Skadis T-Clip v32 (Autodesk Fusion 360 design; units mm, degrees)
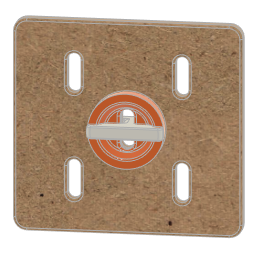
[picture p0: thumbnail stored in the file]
parameter "AttachmentSlotAngle" = 0
parameter "ClipLengthTolerance" = -0.1 comment "This determines how  tight  the clip fastens together."
parameter "PaintedSkadisThickness" = 5.25
parameter "UnpaintedSkadisThickness" = 4.82
parameter "ResultingClipLength" = 4.72 (= "SkadisBoardThickness + ClipLengthTolerance")
ground "Ground1"
sketch "Skadis Hole Dimensions" plane through (0, 0, 0) normal (0, 1, 0) x axis (1, 0, 0)
  line L1 (-2.5, -5) -> (-2.5, 5)
  line L2 (2.5, 5) -> (2.5, -5)
  line L3 (0, 7.5) -> (0, -7.5)
  arc A1 centre (0, -5) radius 2.5 clockwise from (2.5, -5) to (-2.5, -5)
  arc A2 centre (0, 5) radius 2.5 clockwise from (-2.5, 5) to (2.5, 5)
  point P8 (0, -7.5)
  point P9 (0, 7.5)
  point P10 (0, -7.5)
  point P11 (0, 7.5)
  point P1 (0, 0)
  point P3 (-2.5, -5)
  point P4 (2.5, -5)
  tangent L1 A1
  tangent A1 L2
  parallel L1 L2
  tangent L2 A2
  tangent L1 A2
  midpoint A1 P8
  midpoint A2 P9
  coincident P8 P10
  coincident P9 P11
  midpoint P1 L3
  vertical L3
  dimension "d1" distance P3 P4 = 5
  dimension "d39" distance P8 P9 = 15
sketch "Skadis Board Thickness" plane through (0, 0, 0) normal (1, 0, 0) x axis (0, 1, 0)
  line L1 (4.82, 0) -> (0, 0)
  point P1 (0, 0)
  point P2 (0, 0)
  point P3 (4.82, 0)
  horizontal L1
  coincident P1 P2
  dimension "SkadisBoardThickness" distance P2 P3 = 4.82 (= "UnpaintedSkadisThickness")
sketch "Reference Skadis Shape" plane through (0, 0, 0) normal (0, 1, 0) x axis (1, 0, 0)
  line L1 (2.5, 5) -> (2.5, -5)
  line L2 (-2.5, -5) -> (-2.5, 5)
  line L3 (22.5, -15) -> (22.5, -25)
  line L4 (17.5, -25) -> (17.5, -15)
  line L5 (20, -15) -> (20, -25)
  line L6 (0, 7.5) -> (0, -7.5)
  line L7 (2.5, 0) -> (-2.5, 0)
  line L8 (17.5, 25) -> (17.5, 15)
  line L9 (22.5, 15) -> (22.5, 25)
  line L10 (-17.5, -25) -> (-17.5, -15)
  line L11 (-22.5, -15) -> (-22.5, -25)
  line L12 (-17.5, 25) -> (-17.5, 15)
  line L13 (-22.5, 15) -> (-22.5, 25)
  line L14 (-37.5, 40) -> (37.5, 40)
  line L15 (-42.5, -35) -> (-42.5, 35)
  line L16 (37.5, -40) -> (-37.5, -40)
  line L17 (42.5, 35) -> (42.5, -35)
  line L18 (-42.5, -40) -> (42.5, 40)
  line L19 (42.5, -40) -> (-42.5, 40)
  line L20 (0, 40) -> (0, -40)
  arc A1 centre (0, -5) radius 2.5 clockwise from (2.5, -5) to (-2.5, -5)
  arc A2 centre (0, 5) radius 2.5 clockwise from (-2.5, 5) to (2.5, 5)
  arc A3 centre (20, -15) radius 2.5 clockwise from (17.5, -15) to (22.5, -15)
  arc A4 centre (20, -25) radius 2.5 clockwise from (22.5, -25) to (17.5, -25)
  arc A5 centre (20, 25) radius 2.5 clockwise from (17.5, 25) to (22.5, 25)
  arc A6 centre (20, 15) radius 2.5 clockwise from (22.5, 15) to (17.5, 15)
  arc A7 centre (-20, -25) radius 2.5 clockwise from (-17.5, -25) to (-22.5, -25)
  arc A8 centre (-20, -15) radius 2.5 clockwise from (-22.5, -15) to (-17.5, -15)
  arc A9 centre (-20, 15) radius 2.5 clockwise from (-17.5, 15) to (-22.5, 15)
  arc A10 centre (-20, 25) radius 2.5 clockwise from (-22.5, 25) to (-17.5, 25)
  arc A11 centre (-37.5, -35) radius 5 clockwise from (-37.5, -40) to (-42.5, -35)
  arc A12 centre (37.5, -35) radius 5 clockwise from (42.5, -35) to (37.5, -40)
  arc A13 centre (37.5, 35) radius 5 clockwise from (37.5, 40) to (42.5, 35)
  arc A14 centre (-37.5, 35) radius 5 clockwise from (-42.5, 35) to (-37.5, 40)
  point P18 (20, -20)
  point P19 (0, -7.5)
  point P20 (0, 7.5)
  point P21 (0, 0)
  point P22 (-2.5, 0)
  point P23 (2.5, 0)
  point P12 (22.5, -25)
  point P27 (22.5, 25)
  point P13 (22.5, -15)
  point P29 (22.5, 15)
  point P14 (17.5, -15)
  point P24 (17.5, 15)
  point P15 (17.5, -25)
  point P25 (17.5, 25)
  point P33 (-22.5, -25)
  point P35 (-22.5, -15)
  point P30 (-17.5, -15)
  point P31 (-17.5, -25)
  point P37 (-17.5, 15)
  point P39 (-17.5, 25)
  point P41 (-22.5, 25)
  point P38 (-22.5, 15)
  point P46 (0, 0)
  point P44 (-42.5, -40)
  point P45 (42.5, -40)
  point P42 (42.5, 40)
  point P43 (-42.5, 40)
  point P59 (0, -40)
  point P60 (0, 40)
  point P6 (0, -5)
  point P17 (20, -15)
  tangent L3 A3
  tangent A3 L4
  parallel L3 L4
  tangent L4 A4
  tangent L3 A4
  vertical L5
  midpoint L5 P18
  equal A1 A4
  equal L1 L3
  midpoint A1 P19
  midpoint A2 P20
  coincident L6 P21
  midpoint L6 P21
  midpoint L2 P22
  midpoint L1 P23
  symmetric P12 L7 P27
  symmetric P13 L7 P29
  symmetric P14 L7 P24
  symmetric P15 L7 P25
  symmetric A3 L7 A6
  symmetric A4 L7 A5
  symmetric P12 L6 P33
  symmetric P13 L6 P35
  symmetric P14 L6 P30
  symmetric P15 L6 P31
  symmetric A3 L6 A8
  symmetric A4 L6 A7
  symmetric L6 P24 P37
  symmetric L6 P25 P39
  symmetric L6 P27 P41
  symmetric L6 A5 A10
  symmetric L6 P29 P38
  symmetric L6 A6 A9
  horizontal L14
  perpendicular L14 L15
  parallel L14 L16
  parallel L15 L17
  coincident L18 P46
  coincident L19 P46
  coincident P21 P46
  coincident P44 L15
  coincident P44 L16
  tangent L15 A11
  tangent L16 A11
  coincident P45 L16
  coincident P45 L17
  tangent L16 A12
  tangent L17 A12
  coincident P42 L17
  coincident P42 L14
  tangent L17 A13
  tangent L14 A13
  equal A12 A13
  coincident P43 L14
  coincident P43 L15
  tangent L14 A14
  tangent L15 A14
  equal A12 A14
  equal A11 A12
  midpoint L16 P59
  midpoint L14 P60
  dimension "d4" distance P6 P17 = 20
  dimension "d5" distance P18 P21 = 20
  dimension "d6" distance P33 L15 = 20
  dimension "d7" distance P18 L16 = 20
  dimension "d8" radius A11 = 5
extrude "Extrude1" sketch "Reference Skadis Shape" profile of L1 A1 A2 L2 L3 A3 L4 A4 L8 A5 A6 L9 L10 A7 A8 L11 A9 L12 A10 L13 L14 L15 L16 L17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 to an object
fillet "Fillet1" radius 1
sketch "Cross Section Cut Profile" plane through (0, 0, 0) normal (0, 1, 0) x axis (1, 0, 0)
  line L1 (37.5, -40) -> (-37.5, -40)
  line L2 (-37.5, 40) -> (37.5, 40)
  line L3 (-42.5, -35) -> (-42.5, 35)
  line L4 (0, 40) -> (0, -40)
  line L5 (-42.5, -40) -> (-37.5, -40)
  line L6 (-42.5, -40) -> (-42.5, -35)
  line L7 (-42.5, 40) -> (-42.5, 35)
  line L8 (-37.5, 40) -> (-42.5, 40)
  point P8 (0, -40)
  point P9 (0, 40)
  point P2 (-37.5, -40)
  point P10 (-37.5, -40)
  point P7 (-42.5, -35)
  point P12 (-42.5, -35)
  point P6 (-42.5, 35)
  point P13 (-42.5, 35)
  point P5 (-37.5, 40)
  point P15 (-37.5, 40)
  midpoint L1 P8
  coincident L2 P9
  vertical L4
  coincident P2 P10
  coincident P7 P12
  collinear L3 L6
  collinear L1 L5
  coincident P6 P13
  coincident P5 P15
  collinear L2 L8
  collinear L3 L7
extrude "Extrude2" cut sketch "Cross Section Cut Profile" no distance stored
sketch "Part Minimum Thickness" plane through (0, 0, 0) normal (1, 0, 0) x axis (0, 1, 0)
  line L1 (0, -7.5) -> (0, 7.5)
  line L2 (-2.4, 0) -> (0, 0)
  point P6 (0, 0)
  point P7 (-2.4, 0)
  perpendicular L1 L2
  midpoint L1 P6
  dimension "PartMinimumThickness" distance P6 P7 = 2.4
sketch "End Peg Tolerance" plane through (0, 0, 0) normal (0, 1, 0) x axis (1, 0, 0)
  line L1 (-2.5, -5) -> (-2.5, 5)
  line L2 (2.5, 5) -> (2.5, -5)
  line L3 (2.4, 5) -> (2.4, -5)
  line L4 (-2.4, -5) -> (-2.4, 5)
  line L5 (0, 7.4) -> (0, -7.4)
  line L6 (2.4, 0) -> (-2.4, 0)
  arc A1 centre (0, 5) radius 2.5 clockwise from (-2.5, 5) to (2.5, 5)
  arc A2 centre (0, -5) radius 2.5 clockwise from (2.5, -5) to (-2.5, -5)
  arc A3 centre (0, -5) radius 2.4 clockwise from (2.4, -5) to (-2.4, -5)
  arc A4 centre (0, 5) radius 2.4 clockwise from (-2.4, 5) to (2.4, 5)
  point P18 (0, -7.4)
  point P19 (0, 7.4)
  point P20 (-2.4, 0)
  point P21 (2.4, 0)
  midpoint A3 P18
  midpoint A4 P19
  coincident L4 P20
  coincident L3 P21
  midpoint L4 P20
  midpoint L3 P21
  dimension "EndPegTolerance" = -0.1
sketch "End Peg Length" plane through (0, 0, 0) normal (1, 0, 0) x axis (0, 1, 0)
  line L1 (0, -7.4) -> (0, 7.4)
  line L2 (4.72, 7.4) -> (0, 7.4)
  line L3 (4.72, -7.4) -> (0, -7.4)
  line L4 (4.72, -7.4) -> (4.72, 7.4)
  line L5 (4.82, 0) -> (0, 0)
  line L6 (9.72, 7.4) -> (4.72, 7.4)
  line L7 (9.72, -7.4) -> (9.72, 7.4)
  line L8 (4.72, -7.4) -> (9.72, -7.4)
  point P2 (0, 7.4)
  point P4 (0, 7.4)
  point P3 (0, -7.4)
  point P6 (0, -7.4)
  point P5 (4.72, 7.4)
  point P10 (9.72, 7.4)
  coincident P2 P4
  perpendicular L1 L2
  coincident P3 P6
  perpendicular L1 L3
  parallel L1 L4
  perpendicular L4 L6
  perpendicular L4 L8
  parallel L4 L7
  dimension "d20" distance P5 P10 = 5
  dimension "d115" distance P4 P5 = 4.72 (= "ResultingClipLength")
extrude "Extrude2" sketch "End Peg Tolerance" profile of A3 L4 L3 A4 to an object
sketch "End Twist Position" plane through (0, 0, 0) normal (0, 1, 0) x axis (1, 0, 0)
  line L1 (-2.5, -5) -> (-2.5, 5)
  line L2 (2.5, 5) -> (2.5, -5)
  line L3 (0, 7.5) -> (0, -7.5)
  line L4 (5, -2.5) -> (-5, -2.5)
  line L5 (-5, 2.5) -> (5, 2.5)
  line L6 (7.5, 0) -> (-7.5, 0)
  arc A1 centre (0, 5) radius 2.5 clockwise from (-2.5, 5) to (2.5, 5)
  arc A2 centre (0, -5) radius 2.5 clockwise from (2.5, -5) to (-2.5, -5)
  arc A3 centre (5, 0) radius 2.5 clockwise from (5, 2.5) to (5, -2.5)
  arc A4 centre (-5, 0) radius 2.5 clockwise from (-5, -2.5) to (-5, 2.5)
  point P20 (-7.5, 0)
  point P21 (7.5, 0)
  point P22 (0, 0)
  point P1 (0, 0)
  tangent L4 A3
  tangent A3 L5
  parallel L4 L5
  tangent L5 A4
  tangent L4 A4
  midpoint A4 P20
  midpoint A3 P21
  coincident L3 P22
  midpoint L3 P22
  midpoint P1 L6
  equal L3 L6
  equal A2 A3
  dimension "TwistLimitAngle" angle L3 L6 = 90
sketch "Twist Shaft Profile" plane through (0, 0, 0) normal (0, 1, 0) x axis (1, 0, 0)
  line L1 (-5, 2.5) -> (5, 2.5)
  line L2 (5, -2.5) -> (-5, -2.5)
  line L3 (-2.4, -5) -> (-2.4, 5)
  line L4 (2.4, 5) -> (2.4, -5)
  line L5 (0, 2.5) -> (0, -2.5)
  line L6 (-2.4, 0) -> (2.4, 0)
  line L7 (0, -2.5) -> (0.672, -2.304)
  line L8 (0, 2.5) -> (-0.672, 2.304)
  line L9 (0, 2.5) -> (0, -2.5)
  line L10 (-2.4, -2.5) -> (0, -2.5)
  line L11 (2.4, 2.5) -> (0, 2.5)
  line L12 (1.7313, 1.8035) -> (2.4, 2.5)
  line L13 (-1.7313, -1.8035) -> (-2.4, -2.5)
  arc A1 centre (-5, 0) radius 2.5 clockwise from (-5, -2.5) to (-5, 2.5)
  arc A2 centre (5, 0) radius 2.5 clockwise from (5, 2.5) to (5, -2.5)
  arc A3 centre (0, 5) radius 2.4 clockwise from (-2.4, 5) to (2.4, 5)
  arc A4 centre (0, -5) radius 2.4 clockwise from (2.4, -5) to (-2.4, -5)
  arc A5 centre (0, 0) radius 2.4 clockwise from (2.4, 0) to (0.672, -2.304)
  arc A6 centre (0, 0) radius 2.4 clockwise from (-2.4, 0) to (-0.672, 2.304)
  arc A7 centre (0, 0) radius 2.5 clockwise from (0, -2.5) to (-1.7313, -1.8035)
  arc A8 centre (0, 0) radius 2.5 clockwise from (0, 2.5) to (1.7313, 1.8035)
  point P22 (0, -2.5)
  point P23 (0, 2.5)
  point P24 (2.4, 0)
  point P25 (-2.4, 0)
  point P1 (0, 0)
  point P26 (0, 0)
  point P28 (0, 0)
  point P32 (0, 0)
  point P33 (-2.4, -2.5)
  point P34 (2.4, 2.5)
  point P35 (0, 0)
  point P31 (0, -2.5)
  point P37 (0, 0)
  coincident L2 P22
  coincident L1 P23
  perpendicular L1 L5
  midpoint L2 P22
  midpoint L4 P24
  midpoint L3 P25
  coincident P1 P26
  tangent A5 L7
  coincident P26 P28
  tangent A6 L8
  midpoint L9 P32
  coincident L3 P33
  coincident L4 P34
  coincident P1 P35
  coincident P31 A7
  tangent L10 A7
  coincident P28 P37
  tangent L11 A8
  collinear L12 L13
  dimension "d85" angle L6 L9 = 90 (= "TwistLimitAngle")
extrude "Extrude1" sketch "Twist Shaft Profile" profile of L3 L4 A5 L7 A6 L8 L10 L11 A7 A8 to an object
chamfer "Chamfer1" distance 1.5
extrude "Extrude3" sketch "Twist Shaft Profile" profile of L3 L4 to an object
sketch "M3 Position" plane through (0, 0, 0) normal (1, 0, 0) x axis (0, 1, 0)
  line L1 (-2.4, 0) -> (0, 0)
  line L2 (-5.58, 2.65) -> (-5.58, 1.47)
  line L3 (-8.67, 2.65) -> (-5.58, 2.65)
  line L4 (-8.67, -2.65) -> (-8.67, 2.65)
  line L5 (-5.58, -2.65) -> (-8.67, -2.65)
  line L6 (-5.58, -1.47) -> (-5.58, -2.65)
  line L7 (8.42, -1.47) -> (-5.58, -1.47)
  line L8 (8.42, 1.47) -> (8.42, -1.47)
  line L9 (-5.58, 1.47) -> (8.42, 1.47)
  line L10 (9.92, -7.4) -> (9.92, 7.4)
  line L11 (8.42, 0) -> (9.92, 0)
  line L12 (-5.58, -1.47) -> (-5.58, 1.47)
  line L13 (-8.67, 0) -> (8.42, 0)
  point P14 (9.92, 0)
  point P15 (8.42, 0)
  point P16 (-8.67, 0)
  point P6 (-8.67, 2.65)
  point P7 (-8.67, -2.65)
  point P10 (8.42, -1.47)
  point P11 (8.42, 1.47)
  point P5 (-5.58, 2.65)
  point P4 (-5.58, 1.47)
  point P3 (-2.4, 0)
  perpendicular L2 L3
  perpendicular L3 L4
  perpendicular L4 L5
  perpendicular L5 L6
  perpendicular L6 L7
  horizontal L9
  collinear L2 L6
  equal L2 L6
  midpoint L10 P14
  midpoint L8 P15
  horizontal L11
  parallel L7 L9
  perpendicular L8 L9
  midpoint L4 P16
  dimension "d60" distance P6 P7 = 5.3
  dimension "d61" distance P10 P11 = 2.94
  dimension "d62" distance P5 P6 = 3.09
  dimension "d63" distance P14 P15 = 1.5
  dimension "d64" distance P4 P11 = 14
  dimension "d95" distance P3 P4 = 3.18
revolve "Revolve1" sketch "M3 Position" AlongAngle 360
sketch "Hex Hole (Decorative)" plane through (0, -8.67, 0) normal (0, -1, 0) x axis (1, 0, 0)
  line L1 (-1.2341, 0.7125) -> (0, 1.425)
  line L2 (-1.2341, -0.7125) -> (-1.2341, 0.7125)
  line L3 (0, -1.425) -> (-1.2341, -0.7125)
  line L4 (1.2341, -0.7125) -> (0, -1.425)
  line L5 (1.2341, 0.7125) -> (1.2341, -0.7125)
  line L6 (0, 1.425) -> (1.2341, 0.7125)
  circle C1 centre (0, 0) radius 2.65
  point P2 (0, 0)
  point P9 (0, 0)
  point P4 (-1.2341, 0.7125)
  point P7 (1.2341, -0.7125)
  coincident P2 P9
  vertical L2
  dimension "d68" distance P4 P7 = 2.85
extrude "Extrude1" cut sketch "Hex Hole (Decorative)" profile of L1 L2 L3 L4 L5 L6 against normal blind 1.7
fillet "Fillet1" radius 0.1
sketch "Handle Space Limitations" plane through (0, 0, 0) normal (0, 1, 0) x axis (1, 0, 0)
  line L1 (20, -15) -> (20, -25)
  line L2 (22.5, -15) -> (22.5, -25)
  line L3 (17.5, -25) -> (17.5, -15)
  line L4 (0, 7.5) -> (0, -7.5)
  arc A1 centre (20, -15) radius 2.5 clockwise from (17.5, -15) to (22.5, -15)
  arc A2 centre (20, -25) radius 2.5 clockwise from (22.5, -25) to (17.5, -25)
  circle C1 centre (20, -20) radius 14.1421
  circle C2 centre (0, 0) radius 14.1421
  point P14 (20, -20)
  point P17 (0, 0)
  midpoint L1 P14
  coincident L4 P17
  tangent C1 C2
  midpoint L4 P17
  equal C1 C2
  dimension "d142" diameter C2 = 28.2843
as_built_joint "As-built1" OffsetX 0 OffsetY 0 OffsetZ 0 AngleZ 0
sketch "Attachment Slot Angle" plane through (0, 0, 0) normal (0, 1, 0) x axis (1, 0, 0)
  line L1 (-2.4, -5) -> (-2.4, 5)
  line L2 (2.4, 5) -> (2.4, -5)
  line L3 (0, -5) -> (0, 5)
  line L4 (2.6, 0) -> (0, 0)
  line L5 (-2.6, -5) -> (-2.6, 5)
  line L6 (2.6, 5) -> (2.6, -5)
  line L7 (-2.4, -5) -> (-2.4, 5)
  line L8 (2.4, 5) -> (2.4, -5)
  line L9 (0, 7.4) -> (0, -7.4)
  arc A1 centre (0, -5) radius 2.4 clockwise from (2.4, -5) to (-2.4, -5)
  arc A2 centre (0, 5) radius 2.4 clockwise from (-2.4, 5) to (2.4, 5)
  arc A3 centre (0, 5) radius 2.6 clockwise from (-2.6, 5) to (2.6, 5)
  arc A4 centre (0, -5) radius 2.6 clockwise from (2.6, -5) to (-2.6, -5)
  arc A5 centre (0, 5) radius 2.4 clockwise from (-2.4, 5) to (2.4, 5)
  arc A6 centre (0, -5) radius 2.4 clockwise from (2.4, -5) to (-2.4, -5)
  point P1 (0, 0)
  point P8 (0, 0)
  point P9 (0, 0)
  point P10 (2.6, 0)
  tangent L1 A1
  tangent A1 L2
  parallel L1 L2
  tangent L2 A2
  tangent L1 A2
  coincident P1 P8
  midpoint L3 P8
  coincident P1 P9
  horizontal L4
  equal L2 L8
  equal A1 A6
  coincident P10 L6
  dimension "d90" angle L3 L4 = 90 (= "AttachmentSlotAngle + 90 deg")
  dimension "AttachmentSlotTolerance" = 0.2
position "Position1"
sketch "Minimum Material Profile" plane through (0, 0, 0) normal (0, 1, 0) x axis (1, 0, 0)
  line L1 (2.6, 5) -> (2.6, -5)
  line L2 (-2.6, -5) -> (-2.6, 5)
  line L3 (2.5, -2.4) -> (2.5, 0)
  line L4 (-2.5, 2.4) -> (-2.5, 0)
  line L5 (0, 3.4655) -> (0, -3.4655)
  circle C1 centre (0, 0) radius 14.1421
  arc A1 centre (0, 5) radius 2.6 clockwise from (-2.6, 5) to (2.6, 5)
  arc A2 centre (0, -5) radius 2.6 clockwise from (2.6, -5) to (-2.6, -5)
  arc A3 centre (0, 0) radius 3.4655 clockwise from (-2.5, 2.4) to (0, 3.4655)
  arc A4 centre (0, 0) radius 3.4655 clockwise from (2.5, -2.4) to (0, -3.4655)
  point P15 (-2.5, 2.4)
  point P19 (-2.5, 2.4)
  point P2 (0, 0)
  point P17 (0, 0)
  point P14 (2.5, -2.4)
  point P22 (2.5, -2.4)
  point P20 (0, 0)
  point P1 (0, 0)
  coincident P15 P19
  coincident P2 P17
  coincident P14 P22
  coincident P17 P20
  midpoint P1 L5
  vertical L5
extrude "Extrude1" new body sketch "Minimum Material Profile" profile of C1 A1 L1 A2 L2 L3 L4 A3 A4 to an object bodies "Attached Part"
sketch "(Reference) Diameter of Slot" plane through (0, 0, 0) normal (0, 1, 0) x axis (1, 0, 0)
  arc A1 centre (0, 5) radius 2.6 clockwise from (-2.6, 5) to (2.6, 5)
  arc A2 centre (0, -5) radius 2.6 clockwise from (2.6, -5) to (-2.6, -5)
  circle C1 centre (0, 0) radius 7.6
  point P1 (0, 0)
  point P8 (0, 0)
  point P9 (0, -7.6)
  coincident P1 P8
  midpoint A2 P9
  coincident C1 P9
sketch "Handle Seat Profile" plane through (0, 0, 0) normal (1, 0, 0) x axis (0, 1, 0)
  line L1 (0, 7.6) -> (0, -7.6)
  line L2 (-2.4, 0) -> (0, 0)
  line L3 (-2.4, -7.7) -> (-2.4, 7.7)
  line L4 (-2.4, 7.6) -> (0, 7.6)
  line L5 (-5.4, 10.6836) -> (-2.7572, 8.466)
  line L6 (-5.4, 14.1421) -> (0, 14.1421)
  line L7 (-5.4, 10.6836) -> (-5.4, 14.1421)
  line L8 (-2.4, 14.1421) -> (-2.4, 7.7)
  arc A1 centre (-3.4, 7.7) radius 1 clockwise from (-2.7572, 8.466) to (-2.4, 7.7)
  point P5 (-2.4, 0)
  point P3 (0, 7.6)
  point P8 (0, 7.6)
  point P12 (0, 14.1421)
  point P14 (0, 14.1421)
  point P16 (-2.4, 14.1421)
  point P17 (-2.4, 7.6)
  point P6 (-2.4, 7.7)
  point P11 (-5.4, 10.6836)
  parallel L1 L3
  midpoint P5 L3
  coincident P3 P8
  horizontal L4
  tangent L3 A1
  tangent A1 L5
  coincident P12 P14
  horizontal L6
  vertical L7
  coincident L6 P16
  tangent A1 L8
  parallel L3 L8
  coincident L3 P17
  dimension "d97" angle L4 L5 = 40
  dimension "d98" radius A1 = 1
  dimension "d99" distance P6 P11 = 3
  dimension "d138" distance P6 P17 = 0.1
revolve "Revolve1" sketch "Handle Seat Profile" AlongAngle 360
as_built_joint "As-built2" OffsetX 0 OffsetY 0 OffsetZ 0 AngleZ 0
sketch "Handle Tolerances" plane through (0, 0, 0) normal (1, 0, 0) x axis (0, 1, 0)
  line L1 (-2.7572, 8.466) -> (-5.4, 10.6836)
  line L2 (-2.755, 8.3989) -> (-5.401, 10.6192)
  line L3 (-2.4, 0) -> (0, 0)
  line L4 (-2.4, 0) -> (-2.4, 7.7)
  line L5 (-5.4, 14.1421) -> (0, 14.1421)
  line L6 (-5.401, 14.1421) -> (-5.4, 14.1421)
  line L7 (-5.401, 10.6192) -> (-5.401, 14.1421)
  arc A1 centre (-3.4, 7.7) radius 1 between (-2.4, 7.7) and (-2.7572, 8.466)
  arc A2 centre (-3.3977, 7.6328) radius 1 clockwise from (-2.755, 8.3989) to (-2.4, 7.7)
  point P1 (0, 0)
  point P11 (0, 0)
  point P3 (-2.4, 7.7)
  point P13 (-2.4, 7.7)
  point P9 (-2.4, 7.7)
  point P15 (-5.4, 14.1421)
  point P16 (-5.4, 14.1421)
  point P5 (-5.4, 10.6836)
  point P7 (-5.401, 10.6192)
  parallel L1 L2
  tangent L2 A2
  equal A1 A2
  coincident P1 P11
  horizontal L3
  coincident P3 P13
  vertical L4
  coincident P9 P13
  coincident P15 P16
  parallel L5 L6
  vertical L7
  dimension "d102" distance L1 L2 = 0.05
  dimension "d104" distance P5 P7 = 0.001
sketch "Handle Profile" plane through (0, 0, 0) normal (1, 0, 0) x axis (0, 1, 0)
  line L1 (-2.4, 0) -> (-2.4, 7.7)
  line L2 (-2.755, 8.3989) -> (-5.401, 10.6192)
  line L3 (-5.401, 10.6192) -> (-5.401, 14.1421)
  line L4 (-7.4, 14.1421) -> (-5.401, 14.1421)
  line L5 (-8.9, 0) -> (-8.9, 12.6421)
  line L6 (-2.4, 0) -> (-8.9, 0)
  arc A1 centre (-3.3977, 7.6328) radius 1 clockwise from (-2.755, 8.3989) to (-2.4, 7.7)
  arc A2 centre (-7.4, 12.6421) radius 1.5 clockwise from (-8.9, 12.6421) to (-7.4, 14.1421)
  point P9 (-5.401, 14.1421)
  point P11 (-5.401, 14.1421)
  point P3 (-2.4, 0)
  point P16 (-2.4, 0)
  point P15 (-8.9, 0)
  coincident P9 P11
  perpendicular L3 L4
  tangent L4 A2
  tangent A2 L5
  coincident P3 P16
  horizontal L6
  vertical L5
  dimension "d105" radius A2 = 1.5
  dimension "d106" distance P15 P16 = 6.5
revolve "Revolve1" sketch "Handle Profile" AlongAngle 360
sketch "Cut Handle Flat" plane through (0, 0, 0) normal (0, 1, 0) x axis (1, 0, 0)
  line L1 (-2.4, -5) -> (-2.4, 5)
  line L2 (2.4, 5) -> (2.4, -5)
  line L3 (-2.4, 13.937) -> (-2.4, 5)
  line L4 (-2.4, -13.937) -> (-2.4, -5)
  line L5 (2.4, -13.937) -> (2.4, -5)
  line L6 (2.4, 13.937) -> (2.4, 5)
  circle C1 centre (0, 0) radius 14.1421
  point P2 (-2.4, 5)
  point P7 (-2.4, 5)
  point P8 (-2.4, 13.937)
  point P3 (-2.4, -5)
  point P9 (-2.4, -5)
  point P10 (-2.4, -13.937)
  point P4 (2.4, -5)
  point P11 (2.4, -5)
  point P12 (2.4, -13.937)
  point P5 (2.4, 5)
  point P13 (2.4, 5)
  point P14 (2.4, 13.937)
  coincident P2 P7
  coincident C1 P8
  coincident P3 P9
  coincident C1 P10
  coincident P4 P11
  coincident C1 P12
  coincident P5 P13
  coincident C1 P14
  collinear L2 L6
  collinear L2 L5
  collinear L1 L4
  collinear L1 L3
extrude "Extrude5" cut sketch "Cut Handle Flat" no distance stored
chamfer "Chamfer3" distance 0.5
chamfer "Chamfer4" distance 0.6 distance 1
fillet "Fillet4" radius 2
fillet "Fillet3" radius 1
sketch "Fastener Diameters" plane through (0, 0, 0) normal (0, 1, 0) x axis (1, 0, 0)
  circle C1 centre (0, 0) radius 1.47
  circle C2 centre (0, 0) radius 2.65
  circle C3 centre (0, 0) radius 1.6011
  circle C4 centre (0, 0) radius 2.75
  point P4 (0, 0)
  point P5 (0, 0)
  point P2 (0, -1.47)
  point P3 (0, -2.65)
  point P7 (0, 0)
  coincident P4 P5
  coincident P2 C1
  concentric C1 C2
  coincident P3 C2
  coincident P4 P7
  concentric C2 C4
  dimension "d116" distance C1 C3 = 0.1311
  dimension "d117" distance C2 C4 = 0.1
extrude "Extrude6" sketch "Fastener Diameters" profile of C3 blind -53.225
extrude "Extrude7" sketch "Fastener Diameters" profile of C3 C4 no distance stored
sketch "Aesthetic Stoppers" plane through (0, 0, 0) normal (0, 1, 0) x axis (1, 0, 0)
  line L1 (0, -5) -> (0, 5)
  line L2 (7.3861, 1.3024) -> (-7.3861, -1.3024)
  line L3 (9.6519, 4.342) -> (-10.5549, 0.779)
  line L4 (10.5549, -0.779) -> (-9.6519, -4.342)
  line L5 (-2.6, 10.2593) -> (-2.6, -10.2593)
  line L6 (2.6, 10.2593) -> (2.6, -10.2593)
  line L7 (-2.6, 0) -> (2.6, 0)
  line L8 (-0.4515, 2.5605) -> (0.4515, -2.5605)
  circle C1 centre (0, 0) radius 10.5836
  arc A1 centre (0, -5) radius 2.6 clockwise from (2.6, -5) to (-2.6, -5)
  point P7 (-10.5549, 0.779)
  point P8 (9.6519, 4.342)
  point P9 (-9.6519, -4.342)
  point P10 (10.5549, -0.779)
  point P11 (-2.6, -10.2593)
  point P12 (-2.6, 10.2593)
  point P13 (2.6, -10.2593)
  point P14 (2.6, 10.2593)
  point P15 (2.6, 0)
  point P1 (0, 0)
  point P16 (-2.6, 0)
  point P17 (0.4515, -2.5605)
  point P18 (-0.4515, 2.5605)
  point P19 (-2.6, -5)
  coincident C1 P7
  coincident C1 P8
  coincident C1 P9
  coincident C1 P10
  parallel L2 L4
  parallel L2 L3
  symmetric L2 L3 L4
  coincident C1 P11
  coincident C1 P12
  coincident C1 P13
  coincident C1 P14
  parallel L1 L6
  parallel L1 L5
  symmetric L1 L5 L6
  coincident L6 P15
  coincident P1 L7
  coincident L5 P16
  perpendicular L6 L7
  midpoint L4 P17
  coincident L3 P18
  perpendicular L4 L8
  equal L7 L8
  coincident L5 P19
extrude "Extrude2" add sketch "Aesthetic Stoppers" profile of C1 L3 L4 L5 L6 to an object
fillet "Fillet5" radius 1
fillet "Fillet6" radius 1
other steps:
fillet "Fillet1" radius 1
fillet "Fillet2" radius 1
create_component "CreateComponent1"
create_component "CreateComponent2"
create_component "CreateComponent3"
create_component "CreateComponent1"
named bodies: "Dummy Skadis", "Twist Clip", "Attached Part"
